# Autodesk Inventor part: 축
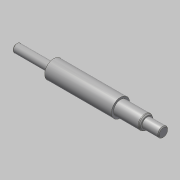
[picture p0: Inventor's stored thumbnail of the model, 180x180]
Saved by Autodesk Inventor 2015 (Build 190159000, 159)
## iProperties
Created: 2016-05
Part Number: 축
Document SubType Name: Modeling
Designer: mduedu
Density: 7.86 g/cm^3
Material: 강철, 연강
Appearance: 강철
Author: mduedu
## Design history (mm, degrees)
sketch "스케치1"
  geometry: L1 (-44, 11)-(-44, 5); L2 (37, 11)-(37, 8.5); L3 (-89, 0)-(89, 0); L4 (-44, 11)-(37, 11); L5 (37, 11)-(37, 8.5); L6 (-44, 11)-(-44, 5); L7 (-44, 5)-(-89, 5); L8 (-89, 5)-(-89, 0); L9 (37, 8.5)-(69, 8.5); L10 (89, 6)-(89, 0); L11 (69, 8.5)-(69, 6); L12 (69, 6)-(89, 6); 1 further point
  constraints: 24 end point, 9 perpendicular, 2 midpoint, 1 horizontal
  dimensions: "d0" = 22 diameter of L4 L3; "d1" = 10 diameter of L7 L3; "d2" = 45 distance between parallel lines of L8 L1; "d3" = 52 distance between parallel lines of L10 L2; "d4" = 12 diameter of L12 L3; "d5" = 20 distance between parallel lines of L10 L11; "d29" = 81 distance of L1.start L2.start; "d37" = 17 diameter of L9 L3
revolve "회전1" stored, may be unused: angle "d6" = 90 deg
chamfer "모따기2" distance "d32" = 1; stored, may be unused: second distance "d33" = 2, angle "d34" = 45 deg
node "작업 평면4"
sketch "스케치4"
  geometry: L1 (-5, 2)-(5, 2); L2 (5, -2)-(-5, -2); L3 (-10, -5)-(-10, 5) reference; A1 r 2 centre (5, 0) between (5, -2) and (5, 2); A2 r 2 centre (-5, 0) between (-5, 2) and (-5, -2); 1 further point
  constraints: 4 end point, 4 point on circle, 4 tangent, 2 centre point, 1 horizontal, 1 horizontal alignment, 1 parallel
  dimensions: "d20" = 4 distance between parallel lines of L2 L1; "d21" = 14 dimension on A1 A2; "d35" = 3 distance edge to line of A2 L3
extrude "돌출3" cut sketch "스케치4" distance "d23" = 2.5; taper "d24" = 0 deg
node "작업 평면5"
sketch "스케치5"
  geometry: L1 (22.5, 1.5)-(12, 1.5); L2 (12, -1.5)-(22.5, -1.5); L3 (22.5, 4)-(22.5, -4) reference; A1 r 1.5 centre (12, 0) between (12, 1.5) and (12, -1.5); 3 further points
  constraints: 4 end point, 2 horizontal alignment, 2 point on circle, 2 point on line, 2 tangent, 1 centre point, 1 coincident, 1 horizontal, 1 midpoint
  dimensions: "d25" = 3 distance between parallel lines of L2 L1; "d36" = 12 dimension on A1 L3
extrude "돌출4" cut sketch "스케치5" distance "d27" = 1.8; taper "d28" = 0 deg
chamfer "모따기3" distance "d38" = 1.82; stored, may be unused: second distance "d39" = 2, angle "d40" = 30 deg
fillet "모깎기1" dims "d41" = 2
node "솔리드1"
